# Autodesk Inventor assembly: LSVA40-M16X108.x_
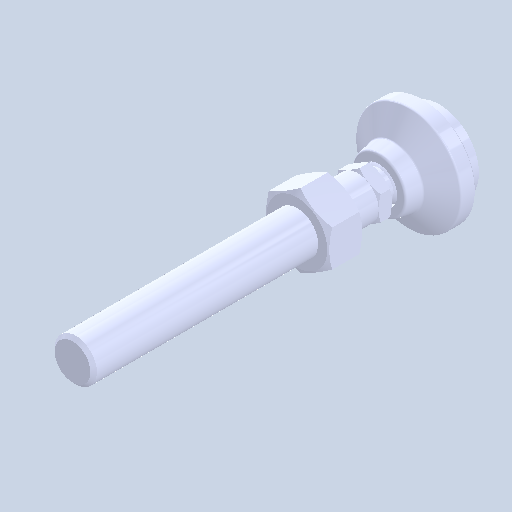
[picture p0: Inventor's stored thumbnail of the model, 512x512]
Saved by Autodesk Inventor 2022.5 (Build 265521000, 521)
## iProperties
Created: 2024-08
Part Number: LSVA40-M16X108.x_
Document SubType Name: Assembly
Designer: ImaoCorp
Author: ImaoCorp
Sending System: SOLIDWORKS 2022-2022290
MC: AMD64
MC_MODEL: Intel64 Family 6 Model 60 Stepping 3, GenuineIntel
OS: Windows_NT
FRU: Parasolid Version 33.1, build 260,  4-25-2022
FORMAT: text
GUISE: transmit
KEY: FILELSVA40-M16X108.x_t
DATE: Fri Aug 23 16:07:38 2024
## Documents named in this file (4)
- X:\14_SW2022-Inv2022\06_2024-10新製品(SME)\ELS_データ\l\lsva40-m16x108\LSVA40-M16X108.x_.iam
- X:\14_SW2022-Inv2022\06_2024-10新製品(SME)\ELS_データ\l\lsva40-m16x108\LSVA40-M16X108_01.ipt
- X:\14_SW2022-Inv2022\06_2024-10新製品(SME)\ELS_データ\l\lsva40-m16x108\LSVA40-M16X108_02.ipt
- X:\14_SW2022-Inv2022\06_2024-10新製品(SME)\ELS_データ\l\lsva40-m16x108\LSVA40-M16X108_03.ipt
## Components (3 placed, 3 different names)
1. LSVA40-M16X108_01
2. LSVA40-M16X108_02
3. LSVA40-M16X108_03
